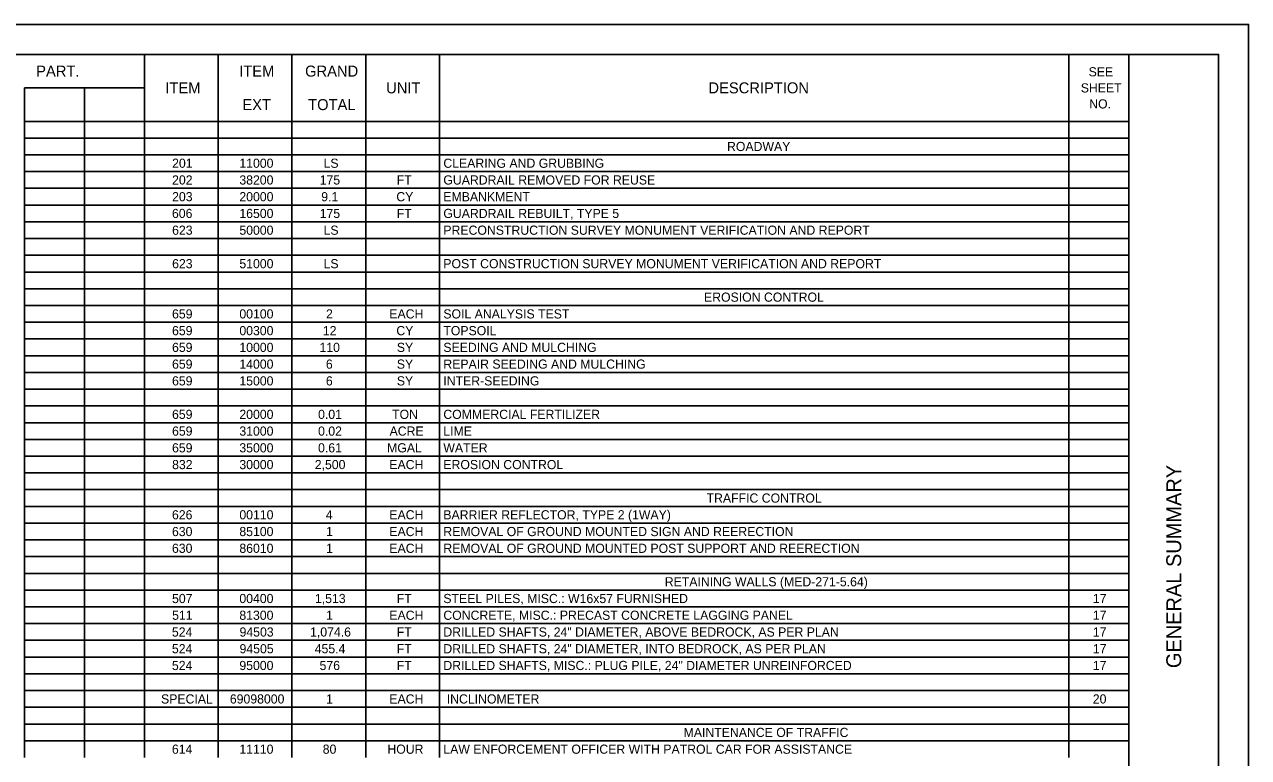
# Model space of a CAD drawing. Extents: x 0 to 34, y 0 to 22.
# Drawn here: x 13.53 to 34, y 9.74 to 22 of the extents above; entities that cross this region are included whole.
import ezdxf

# ---------------------------------------------------------------- set-up
doc = ezdxf.new("R2010")
doc.units = 0
for name, color, linetype in [('Default', 7, 'Continuous'), ('SH_Border', 7, 'Continuous'), ('SH_Cut_Line', 7, 'Continuous'), ('SH_Data', 7, 'Continuous')]:
    doc.layers.add(name, color=color, linetype=linetype)

msp = doc.modelspace()

# ---------------------------------------------------------------- linework, layer by layer
at = {"layer": 'Default'}
for p, q in [((13.53, 21.5), (15.535, 21.5)), ((15.535, 21.5), (32, 21.5)), ((15.535, 21.5), (15.535, 21.22)), ((16.769, 21.5), (16.769, 21.22)), ((18.003, 21.5), (18.003, 21.22)), ((19.237, 21.5), (19.237, 21.22)), ((20.471, 21.5), (20.471, 21.22)), ((30.997, 21.5), (30.997, 21.22)), ((32, 21.5), (32, 21.22)), ((15.535, 21.22), (15.535, 20.94)), ((16.769, 21.22), (16.769, 20.94)), ((18.003, 21.22), (18.003, 20.94)), ((19.237, 21.22), (19.237, 20.94)), ((20.471, 21.22), (20.471, 20.94)), ((30.997, 21.22), (30.997, 20.94)), ((32, 21.22), (32, 20.94)), ((13.53, 20.94), (15.535, 20.94)), ((13.53, 20.94), (13.53, 20.66)), ((14.533, 20.94), (14.533, 20.66)), ((15.535, 20.94), (15.535, 20.66)), ((16.769, 20.94), (16.769, 20.66)), ((18.003, 20.94), (18.003, 20.66)), ((19.237, 20.94), (19.237, 20.66)), ((20.471, 20.94), (20.471, 20.66)), ((30.997, 20.94), (30.997, 20.66)), ((32, 20.94), (32, 20.66)), ((13.53, 20.66), (13.53, 20.38)), ((14.533, 20.66), (14.533, 20.38)), ((15.535, 20.66), (15.535, 20.38)), ((16.769, 20.66), (16.769, 20.38)), ((18.003, 20.66), (18.003, 20.38)), ((19.237, 20.66), (19.237, 20.38)), ((20.471, 20.66), (20.471, 20.38)), ((30.997, 20.66), (30.997, 20.38)), ((32, 20.66), (32, 20.38)), ((13.53, 20.38), (15.535, 20.38)), ((13.53, 20.38), (13.53, 20.1)), ((14.533, 20.38), (14.533, 20.1)), ((15.535, 20.38), (32, 20.38)), ((15.535, 20.38), (15.535, 20.1)), ((16.769, 20.38), (16.769, 20.1)), ((18.003, 20.38), (18.003, 20.1)), ((19.237, 20.38), (19.237, 20.1)), ((20.471, 20.38), (20.471, 20.1)), ((30.997, 20.38), (30.997, 20.1)), ((32, 20.38), (32, 20.1)), ((13.53, 20.1), (15.535, 20.1)), ((13.53, 20.1), (13.53, 18.7)), ((14.533, 20.1), (14.533, 18.7)), ((15.535, 20.1), (32, 20.1)), ((15.535, 20.1), (15.535, 18.7)), ((16.769, 20.1), (16.769, 18.7)), ((18.003, 20.1), (18.003, 18.7)), ((19.237, 20.1), (19.237, 18.7)), ((20.471, 20.1), (20.471, 18.7)), ((30.997, 20.1), (30.997, 18.7)), ((32, 20.1), (32, 18.7)), ((13.53, 19.82), (15.535, 19.82)), ((15.535, 19.82), (32, 19.82)), ((13.53, 19.54), (15.535, 19.54)), ((15.535, 19.54), (32, 19.54)), ((13.53, 19.26), (15.535, 19.26)), ((15.535, 19.26), (32, 19.26)), ((13.53, 18.98), (15.535, 18.98)), ((15.535, 18.98), (32, 18.98)), ((13.53, 18.7), (15.535, 18.7)), ((13.53, 18.7), (13.53, 18.14)), ((14.533, 18.7), (14.533, 18.14)), ((15.535, 18.7), (32, 18.7)), ((15.535, 18.7), (15.535, 18.14)), ((16.769, 18.7), (16.769, 18.14)), ((18.003, 18.7), (18.003, 18.14)), ((19.237, 18.7), (19.237, 18.14)), ((20.471, 18.7), (20.471, 18.14)), ((30.997, 18.7), (30.997, 18.14)), ((32, 18.7), (32, 18.14)), ((13.53, 18.42), (15.535, 18.42)), ((15.535, 18.42), (32, 18.42)), ((13.53, 18.14), (15.535, 18.14)), ((13.53, 18.14), (13.53, 17.86)), ((14.533, 18.14), (14.533, 17.86)), ((15.535, 18.14), (32, 18.14)), ((15.535, 18.14), (15.535, 17.86)), ((16.769, 18.14), (16.769, 17.86)), ((18.003, 18.14), (18.003, 17.86)), ((19.237, 18.14), (19.237, 17.86)), ((20.471, 18.14), (20.471, 17.86)), ((30.997, 18.14), (30.997, 17.86)), ((32, 18.14), (32, 17.86)), ((13.53, 17.86), (15.535, 17.86)), ((13.53, 17.86), (13.53, 17.58)), ((14.533, 17.86), (14.533, 17.58)), ((15.535, 17.86), (32, 17.86)), ((15.535, 17.86), (15.535, 17.58)), ((16.769, 17.86), (16.769, 17.58)), ((18.003, 17.86), (18.003, 17.58)), ((19.237, 17.86), (19.237, 17.58)), ((20.471, 17.86), (20.471, 17.58)), ((30.997, 17.86), (30.997, 17.58)), ((32, 17.86), (32, 17.58)), ((13.53, 17.58), (15.535, 17.58)), ((13.53, 17.58), (13.53, 17.3)), ((14.533, 17.58), (14.533, 17.3)), ((15.535, 17.58), (32, 17.58)), ((15.535, 17.58), (15.535, 17.3)), ((16.769, 17.58), (16.769, 17.3)), ((18.003, 17.58), (18.003, 17.3)), ((19.237, 17.58), (19.237, 17.3)), ((20.471, 17.58), (20.471, 17.3)), ((30.997, 17.58), (30.997, 17.3)), ((32, 17.58), (32, 17.3)), ((13.53, 17.3), (15.535, 17.3)), ((13.53, 17.3), (13.53, 17.02)), ((14.533, 17.3), (14.533, 17.02)), ((15.535, 17.3), (32, 17.3)), ((15.535, 17.3), (15.535, 17.02)), ((16.769, 17.3), (16.769, 17.02)), ((18.003, 17.3), (18.003, 17.02)), ((19.237, 17.3), (19.237, 17.02)), ((20.471, 17.3), (20.471, 17.02)), ((30.997, 17.3), (30.997, 17.02)), ((32, 17.3), (32, 17.02)), ((13.53, 17.02), (15.535, 17.02)), ((13.53, 17.02), (13.53, 16.74)), ((14.533, 17.02), (14.533, 16.74)), ((15.535, 17.02), (32, 17.02)), ((15.535, 17.02), (15.535, 16.74)), ((16.769, 17.02), (16.769, 16.74)), ((18.003, 17.02), (18.003, 16.74)), ((19.237, 17.02), (19.237, 16.74)), ((20.471, 17.02), (20.471, 16.74)), ((30.997, 17.02), (30.997, 16.74)), ((32, 17.02), (32, 16.74)), ((13.53, 16.74), (15.535, 16.74)), ((13.53, 16.74), (13.53, 16.18)), ((14.533, 16.74), (14.533, 16.18)), ((15.535, 16.74), (32, 16.74)), ((15.535, 16.74), (15.535, 16.18)), ((16.769, 16.74), (16.769, 16.18)), ((18.003, 16.74), (18.003, 16.18)), ((19.237, 16.74), (19.237, 16.18)), ((20.471, 16.74), (20.471, 16.18)), ((30.997, 16.74), (30.997, 16.18)), ((32, 16.74), (32, 16.18)), ((13.53, 16.46), (15.535, 16.46)), ((15.535, 16.46), (32, 16.46)), ((13.53, 16.18), (15.535, 16.18)), ((13.53, 16.18), (13.53, 15.9)), ((14.533, 16.18), (14.533, 15.9)), ((15.535, 16.18), (32, 16.18)), ((15.535, 16.18), (15.535, 15.9)), ((16.769, 16.18), (16.769, 15.9)), ((18.003, 16.18), (18.003, 15.9)), ((19.237, 16.18), (19.237, 15.9)), ((20.471, 16.18), (20.471, 15.9)), ((30.997, 16.18), (30.997, 15.9)), ((32, 16.18), (32, 15.9)), ((13.53, 15.9), (15.535, 15.9)), ((13.53, 15.9), (13.53, 15.62)), ((14.533, 15.9), (14.533, 15.62)), ((15.535, 15.9), (32, 15.9)), ((15.535, 15.9), (15.535, 15.62)), ((16.769, 15.9), (16.769, 15.62)), ((18.003, 15.9), (18.003, 15.62)), ((19.237, 15.9), (19.237, 15.62)), ((20.471, 15.9), (20.471, 15.62)), ((30.997, 15.9), (30.997, 15.62)), ((32, 15.9), (32, 15.62)), ((13.53, 15.62), (15.535, 15.62)), ((13.53, 15.62), (13.53, 15.34)), ((14.533, 15.62), (14.533, 15.34)), ((15.535, 15.62), (32, 15.62)), ((15.535, 15.62), (15.535, 15.34)), ((16.769, 15.62), (16.769, 15.34)), ((18.003, 15.62), (18.003, 15.34)), ((19.237, 15.62), (19.237, 15.34)), ((20.471, 15.62), (20.471, 15.34)), ((30.997, 15.62), (30.997, 15.34)), ((32, 15.62), (32, 15.34)), ((13.53, 15.34), (15.535, 15.34)), ((13.53, 15.34), (13.53, 14.78)), ((14.533, 15.34), (14.533, 14.78)), ((15.535, 15.34), (32, 15.34)), ((15.535, 15.34), (15.535, 14.78)), ((16.769, 15.34), (16.769, 14.78)), ((18.003, 15.34), (18.003, 14.78)), ((19.237, 15.34), (19.237, 14.78)), ((20.471, 15.34), (20.471, 14.78)), ((30.997, 15.34), (30.997, 14.78)), ((32, 15.34), (32, 14.78)), ((13.53, 15.06), (15.535, 15.06)), ((15.535, 15.06), (32, 15.06)), ((13.53, 14.78), (15.535, 14.78)), ((13.53, 14.78), (13.53, 14.5)), ((14.533, 14.78), (14.533, 14.5)), ((15.535, 14.78), (32, 14.78)), ((15.535, 14.78), (15.535, 14.5)), ((16.769, 14.78), (16.769, 14.5)), ((18.003, 14.78), (18.003, 14.5)), ((19.237, 14.78), (19.237, 14.5)), ((20.471, 14.78), (20.471, 14.5)), ((30.997, 14.78), (30.997, 14.5)), ((32, 14.78), (32, 14.5)), ((13.53, 14.5), (15.535, 14.5)), ((13.53, 14.5), (13.53, 14.22)), ((14.533, 14.5), (14.533, 14.22)), ((15.535, 14.5), (32, 14.5)), ((15.535, 14.5), (15.535, 14.22)), ((16.769, 14.5), (16.769, 14.22)), ((18.003, 14.5), (18.003, 14.22)), ((19.237, 14.5), (19.237, 14.22)), ((20.471, 14.5), (20.471, 14.22)), ((30.997, 14.5), (30.997, 14.22)), ((32, 14.5), (32, 14.22)), ((13.53, 14.22), (15.535, 14.22)), ((13.53, 14.22), (13.53, 13.94)), ((14.533, 14.22), (14.533, 13.94)), ((15.535, 14.22), (32, 14.22)), ((15.535, 14.22), (15.535, 13.94)), ((16.769, 14.22), (16.769, 13.94)), ((18.003, 14.22), (18.003, 13.94)), ((19.237, 14.22), (19.237, 13.94)), ((20.471, 14.22), (20.471, 13.94)), ((30.997, 14.22), (30.997, 13.94)), ((32, 14.22), (32, 13.94)), ((13.53, 13.94), (15.535, 13.94)), ((13.53, 13.94), (13.53, 11.7)), ((14.533, 13.94), (14.533, 11.7)), ((15.535, 13.94), (32, 13.94)), ((15.535, 13.94), (15.535, 11.7)), ((16.769, 13.94), (16.769, 11.7)), ((18.003, 13.94), (18.003, 11.7)), ((19.237, 13.94), (19.237, 11.7)), ((20.471, 13.94), (20.471, 11.7)), ((30.997, 13.94), (30.997, 11.7)), ((32, 13.94), (32, 11.7)), ((13.53, 13.66), (15.535, 13.66)), ((15.535, 13.66), (32, 13.66)), ((13.53, 13.38), (15.535, 13.38)), ((15.535, 13.38), (32, 13.38)), ((13.53, 13.1), (15.535, 13.1)), ((15.535, 13.1), (32, 13.1)), ((13.53, 12.82), (15.535, 12.82)), ((15.535, 12.82), (32, 12.82)), ((13.53, 12.54), (15.535, 12.54)), ((15.535, 12.54), (32, 12.54)), ((13.53, 12.26), (15.535, 12.26)), ((15.535, 12.26), (32, 12.26)), ((13.53, 11.98), (15.535, 11.98)), ((15.535, 11.98), (32, 11.98)), ((13.53, 11.7), (15.535, 11.7)), ((13.53, 11.7), (13.53, 11.42)), ((14.533, 11.7), (14.533, 11.42)), ((15.535, 11.7), (32, 11.7)), ((15.535, 11.7), (15.535, 11.42)), ((16.769, 11.7), (16.769, 11.42)), ((18.003, 11.7), (18.003, 11.42)), ((19.237, 11.7), (19.237, 11.42)), ((20.471, 11.7), (20.471, 11.42)), ((30.997, 11.7), (30.997, 11.42)), ((32, 11.7), (32, 11.42)), ((13.53, 11.42), (15.535, 11.42)), ((13.53, 11.42), (13.53, 10.3)), ((14.533, 11.42), (14.533, 10.3)), ((15.535, 11.42), (32, 11.42)), ((15.535, 11.42), (15.535, 10.3)), ((16.769, 11.42), (16.769, 10.3)), ((18.003, 11.42), (18.003, 10.3)), ((19.237, 11.42), (19.237, 10.3)), ((20.471, 11.42), (20.471, 10.3)), ((30.997, 11.42), (30.997, 10.3)), ((32, 11.42), (32, 10.3)), ((13.53, 11.14), (15.535, 11.14)), ((15.535, 11.14), (32, 11.14)), ((13.53, 10.86), (15.535, 10.86)), ((15.535, 10.86), (32, 10.86)), ((13.53, 10.58), (15.535, 10.58)), ((15.535, 10.58), (32, 10.58)), ((13.53, 10.3), (15.535, 10.3)), ((13.53, 10.3), (13.53, 10.02)), ((14.533, 10.3), (14.533, 10.02)), ((15.535, 10.3), (32, 10.3)), ((15.535, 10.3), (15.535, 10.02)), ((16.769, 10.3), (16.769, 10.02)), ((18.003, 10.3), (18.003, 10.02)), ((19.237, 10.3), (19.237, 10.02)), ((20.471, 10.3), (20.471, 10.02)), ((30.997, 10.3), (30.997, 10.02)), ((32, 10.3), (32, 10.02)), ((13.53, 10.02), (15.535, 10.02)), ((13.53, 10.02), (13.53, 9.74)), ((14.533, 10.02), (14.533, 9.74)), ((15.535, 10.02), (32, 10.02)), ((15.535, 10.02), (15.535, 9.74)), ((16.769, 10.02), (16.769, 9.74)), ((18.003, 10.02), (18.003, 9.74)), ((19.237, 10.02), (19.237, 9.74)), ((20.471, 10.02), (20.471, 9.74)), ((30.997, 10.02), (30.997, 9.74)), ((32, 10.02), (32, 9.74))]:
    msp.add_line(p, q, dxfattribs=at)
at = {"layer": 'SH_Border'}
msp.add_line((32, 0.5), (32, 21.5), dxfattribs=at)
msp.add_lwpolyline([(1.5, 21.5), (33.5, 21.5), (33.5, 0.5), (1.5, 0.5)], close=True, dxfattribs=at)
at = {"layer": 'SH_Cut_Line'}
msp.add_lwpolyline([(0, 0), (34, 0), (34, 22), (0, 22)], close=True, dxfattribs=at)

# ---------------------------------------------------------------- texts
at = {"layer": 'Default'}
for s, height, p in [('PART.', 0.184, (13.726, 21.128)), ('ITEM', 0.184, (17.121, 21.128)), ('GRAND', 0.184, (18.223, 21.128)), ('SEE ', 0.1533, (31.326, 21.132)), ('ITEM', 0.184, (15.887, 20.848)), ('UNIT', 0.184, (19.578, 20.848)), ('DESCRIPTION', 0.184, (24.968, 20.848)), ('SHEET ', 0.1533, (31.195, 20.863)), ('EXT', 0.184, (17.174, 20.568)), ('TOTAL', 0.184, (18.274, 20.568)), ('NO.', 0.1533, (31.336, 20.595)), ('ROADWAY', 0.1533, (25.279, 19.883)), ('201', 0.1533, (15.999, 19.603)), ('11000', 0.1533, (17.124, 19.603)), ('LS', 0.1533, (18.532, 19.603)), ('CLEARING AND GRUBBING', 0.15333, (20.535, 19.603)), ('202', 0.1533, (15.999, 19.323)), ('38200', 0.1533, (17.124, 19.323)), ('175', 0.1533, (18.467, 19.323)), ('FT', 0.1533, (19.756, 19.323)), ('GUARDRAIL REMOVED FOR REUSE', 0.15333, (20.535, 19.323)), ('203', 0.1533, (15.999, 19.043)), ('20000', 0.1533, (17.124, 19.043)), ('9.1', 0.1533, (18.493, 19.043)), ('CY', 0.1533, (19.749, 19.043)), ('EMBANKMENT', 0.1533, (20.535, 19.043)), ('606', 0.1533, (15.997, 18.763)), ('16500', 0.1533, (17.124, 18.763)), ('175', 0.1533, (18.467, 18.763)), ('FT', 0.1533, (19.756, 18.763)), ('GUARDRAIL REBUILT, TYPE 5', 0.15333, (20.535, 18.763)), ('623', 0.1533, (15.999, 18.483)), ('50000', 0.1533, (17.124, 18.483)), ('LS', 0.1533, (18.532, 18.483)), ('PRECONSTRUCTION SURVEY MONUMENT VERIFICATION AND REPORT', 0.15333, (20.535, 18.483)), ('623', 0.1533, (15.999, 17.923)), ('51000', 0.1533, (17.124, 17.923)), ('LS', 0.1533, (18.532, 17.923)), ('POST CONSTRUCTION SURVEY MONUMENT VERIFICATION AND REPORT', 0.15333, (20.535, 17.923)), ('EROSION CONTROL', 0.15333, (24.894, 17.363)), ('659', 0.1533, (15.998, 17.083)), ('00100', 0.1533, (17.124, 17.083)), ('2', 0.153, (18.573, 17.083)), ('EACH', 0.1533, (19.632, 17.083)), ('SOIL ANALYSIS TEST', 0.15333, (20.535, 17.083)), ('659', 0.1533, (15.998, 16.803)), ('00300', 0.1533, (17.124, 16.803)), ('12', 0.1533, (18.52, 16.803)), ('CY', 0.1533, (19.749, 16.803)), ('TOPSOIL', 0.1533, (20.535, 16.803)), ('659', 0.1533, (15.998, 16.523)), ('10000', 0.1533, (17.124, 16.523)), ('110', 0.1533, (18.464, 16.523)), ('SY', 0.1533, (19.757, 16.523)), ('SEEDING AND MULCHING', 0.15333, (20.535, 16.523)), ('659', 0.1533, (15.998, 16.243)), ('14000', 0.1533, (17.124, 16.243)), ('6', 0.153, (18.571, 16.243)), ('SY', 0.1533, (19.757, 16.243)), ('REPAIR SEEDING AND MULCHING', 0.15333, (20.535, 16.243)), ('659', 0.1533, (15.998, 15.963)), ('15000', 0.1533, (17.124, 15.963)), ('6', 0.153, (18.571, 15.963)), ('SY', 0.1533, (19.757, 15.963)), ('INTER-SEEDING', 0.15333, (20.535, 15.963)), ('659', 0.1533, (15.998, 15.403)), ('20000', 0.1533, (17.124, 15.403)), ('0.01', 0.1533, (18.44, 15.403)), ('TON', 0.1533, (19.678, 15.403)), ('COMMERCIAL FERTILIZER', 0.15333, (20.535, 15.403)), ('659', 0.1533, (15.998, 15.123)), ('31000', 0.1533, (17.124, 15.123)), ('0.02', 0.1533, (18.44, 15.123)), ('ACRE', 0.1533, (19.636, 15.123)), ('LIME', 0.1533, (20.535, 15.123)), ('659', 0.1533, (15.998, 14.843)), ('35000', 0.1533, (17.124, 14.843)), ('0.61', 0.1533, (18.44, 14.843)), ('MGAL', 0.1533, (19.594, 14.843)), ('WATER', 0.1533, (20.535, 14.843)), ('832', 0.1533, (15.999, 14.563)), ('30000', 0.1533, (17.124, 14.563)), ('2,500', 0.1533, (18.385, 14.563)), ('EACH', 0.1533, (19.632, 14.563)), ('EROSION CONTROL', 0.15333, (20.535, 14.563)), ('TRAFFIC CONTROL', 0.15333, (24.937, 14.003)), ('626', 0.1533, (15.997, 13.723)), ('00110', 0.1533, (17.124, 13.723)), ('4', 0.153, (18.57, 13.723)), ('EACH', 0.1533, (19.632, 13.723)), ('BARRIER REFLECTOR, TYPE 2 (1WAY)', 0.15333, (20.535, 13.723)), ('630', 0.1533, (15.997, 13.443)), ('85100', 0.1533, (17.124, 13.443)), ('1', 0.153, (18.573, 13.443)), ('EACH', 0.1533, (19.632, 13.443)), ('REMOVAL OF GROUND MOUNTED SIGN AND REERECTION', 0.15333, (20.535, 13.443)), ('630', 0.1533, (15.997, 13.163)), ('86010', 0.1533, (17.124, 13.163)), ('1', 0.153, (18.573, 13.163)), ('EACH', 0.1533, (19.632, 13.163)), ('REMOVAL OF GROUND MOUNTED POST SUPPORT AND REERECTION', 0.15333, (20.535, 13.163)), ('RETAINING WALLS (MED-271-5.64)', 0.15333, (24.238, 12.603)), ('507', 0.1533, (15.998, 12.323)), ('00400', 0.1533, (17.124, 12.323)), ('1,513', 0.1533, (18.388, 12.323)), ('FT', 0.1533, (19.756, 12.323)), ('STEEL PILES, MISC.: W16x57 FURNISHED', 0.15333, (20.535, 12.323)), ('17', 0.1533, (31.397, 12.323)), ('511', 0.1533, (15.999, 12.043)), ('81300', 0.1533, (17.124, 12.043)), ('1', 0.153, (18.573, 12.043)), ('EACH', 0.1533, (19.632, 12.043)), ('CONCRETE, MISC.: PRECAST CONCRETE LAGGING PANEL', 0.15333, (20.535, 12.043)), ('17', 0.1533, (31.397, 12.043)), ('524', 0.1533, (15.996, 11.763)), ('94503', 0.1533, (17.127, 11.763)), ('1,074.6', 0.1533, (18.306, 11.763)), ('FT', 0.1533, (19.756, 11.763)), ('DRILLED SHAFTS, 24" DIAMETER, ABOVE BEDROCK, AS PER PLAN', 0.15333, (20.535, 11.763)), ('17', 0.1533, (31.397, 11.763)), ('524', 0.1533, (15.996, 11.483)), ('94505', 0.1533, (17.127, 11.483)), ('455.4', 0.1533, (18.384, 11.483)), ('FT', 0.1533, (19.756, 11.483)), ('DRILLED SHAFTS, 24" DIAMETER, INTO BEDROCK, AS PER PLAN', 0.15333, (20.535, 11.483)), ('17', 0.1533, (31.397, 11.483)), ('524', 0.1533, (15.996, 11.203)), ('95000', 0.1533, (17.124, 11.203)), ('576', 0.1533, (18.465, 11.203)), ('FT', 0.1533, (19.756, 11.203)), ('DRILLED SHAFTS, MISC.: PLUG PILE, 24" DIAMETER UNREINFORCED', 0.15333, (20.535, 11.203)), ('17', 0.1533, (31.397, 11.203)), ('SPECIAL', 0.1533, (15.814, 10.643)), ('69098000', 0.1533, (16.965, 10.643)), ('1', 0.153, (18.573, 10.643)), ('EACH', 0.1533, (19.632, 10.643)), (' INCLINOMETER', 0.15333, (20.535, 10.643)), ('20', 0.1533, (31.396, 10.643)), ('MAINTENANCE OF TRAFFIC', 0.15333, (24.553, 10.083)), ('614', 0.1533, (15.996, 9.803)), ('11110', 0.1533, (17.124, 9.803)), ('80', 0.1533, (18.518, 9.803)), ('HOUR', 0.1533, (19.599, 9.803)), ('LAW ENFORCEMENT OFFICER WITH PATROL CAR FOR ASSISTANCE', 0.15333, (20.535, 9.803))]:
    msp.add_text(s, height=height, dxfattribs=at).set_placement(p)
at = {"layer": 'SH_Data'}
msp.add_text('GENERAL SUMMARY', height=0.25, rotation=90, dxfattribs=at).set_placement((32.875, 11.235))

doc.saveas('drawing.dxf')
